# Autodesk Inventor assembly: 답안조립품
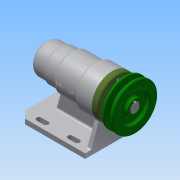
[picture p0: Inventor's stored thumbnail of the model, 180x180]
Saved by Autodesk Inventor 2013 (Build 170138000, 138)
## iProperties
Created: 2017-09
Part Number: 답안조립품
Document SubType Name: Assembly
Designer: Administrator
Author: Administrator
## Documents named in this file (12)
- C:\Users\Administrator\Desktop\470908V1003\답안조립품.iam
- C:\Users\Administrator\Desktop\470908V1003\본체.ipt
- C:\Users\Administrator\Desktop\470908V1003\축.ipt
- C:\Users\Administrator\Desktop\470908V1003\베어링 51202.ipt
- C:\Users\Administrator\Desktop\470908V1003\어댑터슬리브.ipt
- C:\Users\Administrator\Desktop\470908V1003\베어링 6004.ipt
- C:\Users\Administrator\Desktop\470908V1003\볼트 M4 x 12.ipt
- C:\Users\Administrator\Desktop\470908V1003\커버.ipt
- C:\Users\Administrator\Desktop\470908V1003\오일 실 20x35x7.ipt
- C:\Users\Administrator\Desktop\470908V1003\키 5 x 5 x 16.ipt
- C:\Users\Administrator\Desktop\470908V1003\V벨트풀리.ipt
- C:\Users\Administrator\Desktop\470908V1003\멈춤나사 M3x8.ipt
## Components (1 placed, 1 different names)
1. V벨트풀리:1 — 각도:2
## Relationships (1: Angle 1)
- 각도:2 [Angle]: V벨트풀리:1
